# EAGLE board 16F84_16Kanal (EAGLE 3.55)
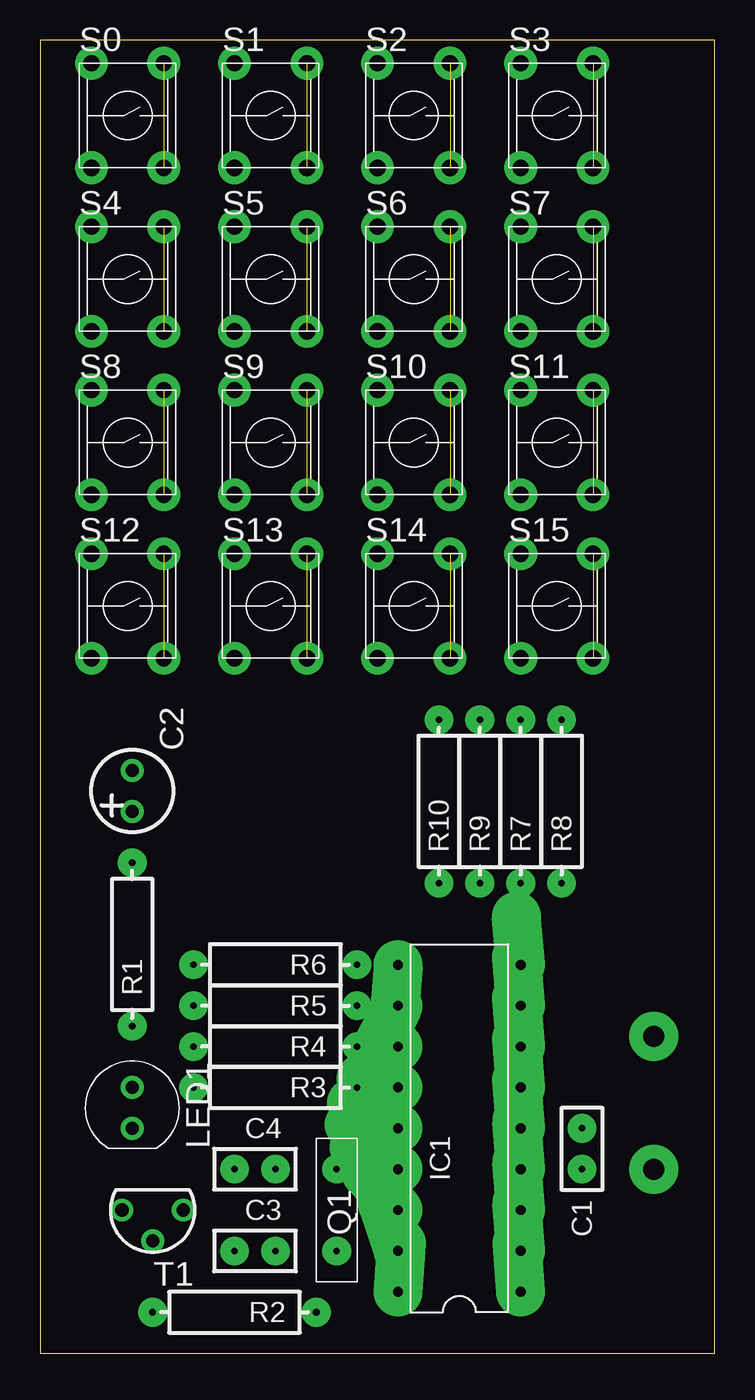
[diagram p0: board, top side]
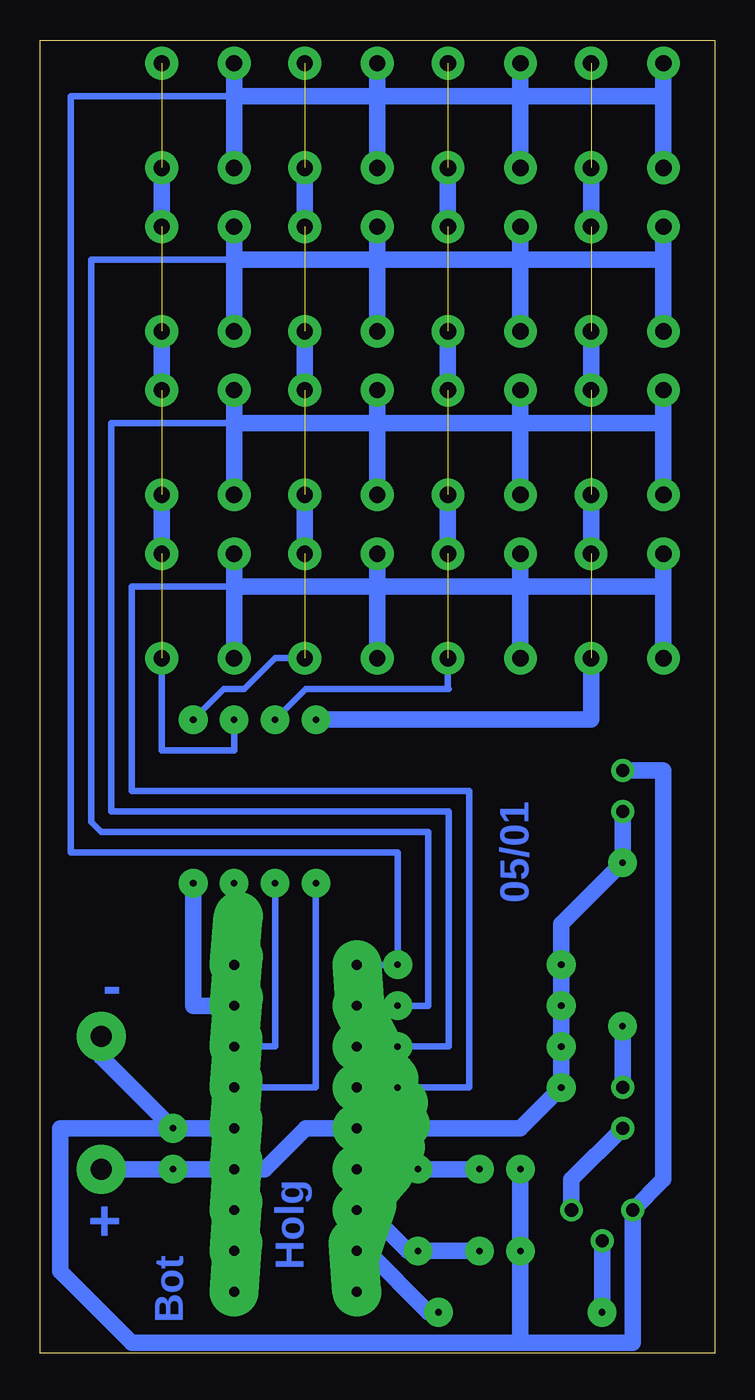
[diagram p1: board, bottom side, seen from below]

Size 41.89 x 81.58 mm. Coordinates in mm from the lower left corner, seen from the top.
Outline: 0,0 41.89,0 41.89,81.58 0,81.58 0,0
Copper layers used: Bottom

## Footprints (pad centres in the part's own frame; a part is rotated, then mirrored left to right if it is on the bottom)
RM2,5 = drill 0.406 pad 1.778 round:  0,0;  2.54,0
KO01 = drill 0.813 pad 1.422 round:  0,0;  2.54,0
L-18B = drill 0.61 pad 3.048 offset:  0,0;  2.54,0;  15.24,0;  17.78,0;  5.08,0;  7.62,0;  12.7,0;  10.16,0;  20.32,0;  20.32,7.62;  17.78,7.62;  15.24,7.62;  12.7,7.62;  10.16,7.62;  7.62,7.62;  5.08,7.62;  2.54,7.62;  0,7.62
D_5MM = drill 0.813 pad 1.422 round:  -1.27,0;  1.27,0
GEL = drill 1.295 pad 3.048 round:  0,0
ARZ_ST = drill 0.406 pad 1.778 round:  0,0;  5.08,0
S04 = drill 0.406 pad 1.778 round:  0,0;  10.16,0
USTAST = drill 1.016 pad 2.032 round:  0,0;  4.5,0;  4.5,6.5;  0,6.5
92 = drill 0.813 pad 1.422 round:  -0.635,0;  1.27,1.905;  3.175,0

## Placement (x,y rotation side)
C1  C100NK  [RM2,5]  33.66,13.97 270 top
C2  100u  [KO01]  5.71,33.66 90 top
C3  27p  [RM2,5]  12.06,6.35 0 top
C4  27p  [RM2,5]  12.06,11.43 0 top
IC1  16F84P  [L-18B]  29.84,3.81 90 top
LED1  LD274  [D_5MM]  5.71,15.24 270 top
N1  +  [GEL]  38.1,11.43 180 top
N2  -  [GEL]  38.1,19.68 180 top
Q1  4MHz  [ARZ_ST]  18.41,11.43 270 top
R1  ???  [S04]  5.71,20.32 90 top
R2  1k  [S04]  17.14,2.54 180 top
R3  100k  [S04]  19.68,16.51 180 top
R4  100k  [S04]  19.68,19.05 180 top
R5  100k  [S04]  19.68,21.59 180 top
R6  100k  [S04]  19.68,24.13 180 top
R7  1k  [S04]  29.84,29.21 90 top
R8  1k  [S04]  32.38,29.21 90 top
R9  1k  [S04]  27.3,29.21 90 top
R10  1k  [S04]  24.77,29.21 90 top
S0  [USTAST]  3.17,73.66 0 top
S1  [USTAST]  12.06,73.66 0 top
S2  [USTAST]  20.95,73.66 0 top
S3  [USTAST]  29.84,73.66 0 top
S4  [USTAST]  3.17,63.5 0 top
S5  [USTAST]  12.06,63.5 0 top
S6  [USTAST]  20.95,63.5 0 top
S7  [USTAST]  29.84,63.5 0 top
S8  [USTAST]  3.17,53.34 0 top
S9  [USTAST]  12.06,53.34 0 top
S10  [USTAST]  20.95,53.34 0 top
S11  [USTAST]  29.84,53.34 0 top
S12  [USTAST]  3.17,43.18 0 top
S13  [USTAST]  12.06,43.18 0 top
S14  [USTAST]  20.95,43.18 0 top
S15  [USTAST]  29.84,43.18 0 top
T1  BC337  [92]  8.26,8.89 180 top

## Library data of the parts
C1 C2 LED1 N1 N2 R1 R2 T1 = holgnorm
C3 C4 IC1 Q1 R3-R10 S0 S1-S15 = holg_plt

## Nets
+UB: C1. C2. IC1. N1. R1. R3. R4. R5. R6.
GND: C1. C2. C3. C4. IC1. N2. T1.
N$1: IC1. R6. S0. S1. S2. S3.
N$2: R2. T1.
N$3: IC1. R7.
N$4: LED1. T1.
N$5: LED1. R1.
N$6: IC1. R2.
N$7: C3. IC1. Q1.
N$8: C4. IC1. Q1.
N$9: IC1. R8.
N$10: IC1. R3. S12. S13. S14. S15.
N$11: IC1. R4. S8. S9. S10. S11.
N$12: IC1. R5. S4. S5. S6. S7.
N$13: IC1. R9.
N$14: R7. S3. S7. S11. S15.
N$15: IC1. R10.
N$17: R8. S2. S6. S10. S14.
N$18: R9. S1. S5. S9. S13.
N$19: R10. S0. S4. S8. S12.

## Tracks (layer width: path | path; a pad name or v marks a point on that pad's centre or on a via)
+UB
  Bottom 1.016: N1. C1. 29.84,11.43 27.94,11.43 25.4,13.97 22.23,13.97 12.06,13.97 R3. R4. R5. R6. 9.53,26.67 R1. 5.71,33.66
GND
  Bottom 0.406: 33.66,13.97 29.84,13.97
  Bottom 1.016: 12.06,11.43 12.06,6.35 12.06,0.64 | 12.06,0.64 5.08,0.64 T1. 3.17,10.79 3.17,36.2 C2. | 33.66,13.97 38.1,18.41 N2. | 33.66,13.97 29.84,13.97 | 33.66,13.97 40.64,13.97 40.64,5.08 36.2,0.64 12.06,0.64
N$1
  Bottom 0.406: 19.68,24.13 22.23,24.13 19.68,24.13 | 19.68,24.13 19.68,31.11 40.01,31.11 40.01,78.11 29.84,78.11
  Bottom 1.016: 3.17,78.11 S0. | 12.06,78.11 3.17,78.11 | 20.95,78.11 12.06,78.11 | 29.84,78.11 20.95,78.11 | 12.06,78.11 S1. | 20.95,78.11 S2. | 29.84,78.11 S3. | 3.17,78.11 3.17,73.66 | 12.06,78.11 12.06,73.66 | 20.95,78.11 20.95,73.66 | 29.84,78.11 29.84,73.66
N$2
  Bottom 1.016: R2. 6.99,6.99
N$3
  Bottom 1.016: 29.84,24.13 29.84,29.21
N$4
  Bottom 1.016: 8.89,8.89 8.89,10.79 LED1.
N$5
  Bottom 1.016: 5.71,16.51 5.71,20.32
N$6
  Bottom 0.406: 17.14,2.54 17.78,2.54
  Bottom 1.016: 22.23,6.35 21.59,6.35 17.78,2.54
N$7
  Bottom 0.406: Q1. 19.05,6.35
  Bottom 1.016: C3. Q1. | 19.05,6.35 21.59,8.89 22.23,8.89
N$8
  Bottom 1.016: 22.23,11.43 18.41,11.43 C4.
N$9
  Bottom 1.016: 29.84,21.59 32.38,21.59 32.38,29.21
N$10
  Bottom 0.406: 19.68,16.51 22.23,16.51 19.68,16.51 | 19.68,16.51 15.24,16.51 15.24,34.92 36.2,34.92 36.2,47.62 29.84,47.62
  Bottom 1.016: 3.17,47.62 S12. | 12.06,47.62 3.17,47.62 | 20.95,47.62 12.06,47.62 | 29.84,47.62 20.95,47.62 | 12.06,47.62 S13. | 20.95,47.62 S14. | 29.84,47.62 S15. | 3.17,47.62 3.17,43.18 | 12.06,47.62 12.06,43.18 | 20.95,47.62 20.95,43.18 | 29.84,47.62 29.84,43.18
N$11
  Bottom 0.406: 19.68,19.05 22.23,19.05 | 19.68,19.05 22.23,19.05 | 19.68,19.05 22.23,19.05 | 19.68,19.05 16.51,19.05 16.51,33.66 37.47,33.66 37.47,57.78 29.84,57.78
  Bottom 1.016: 3.17,57.78 S8. | 12.06,57.78 3.17,57.78 | 20.95,57.78 12.06,57.78 | 29.84,57.78 20.95,57.78 | 12.06,57.78 S9. | 20.95,57.78 S10. | 29.84,57.78 S11. | 3.17,57.78 3.17,53.34 | 12.06,57.78 12.06,53.34 | 20.95,57.78 20.95,53.34 | 29.84,57.78 29.84,53.34
N$12
  Bottom 0.406: 19.68,21.59 22.23,21.59 19.68,21.59 | 19.68,21.59 17.78,21.59 17.78,32.38 38.1,32.38 38.73,33.02 38.73,67.94 29.84,67.94
  Bottom 1.016: 3.17,67.94 S4. | 12.06,67.94 3.17,67.94 | 20.95,67.94 12.06,67.94 | 29.84,67.94 20.95,67.94 | 12.06,67.94 S5. | 20.95,67.94 S6. | 29.84,67.94 S7. | 3.17,67.94 3.17,63.5 | 12.06,67.94 12.06,63.5 | 20.95,67.94 20.95,63.5 | 29.84,67.94 29.84,63.5
N$13
  Bottom 0.406: 29.84,19.05 27.3,19.05 27.3,29.21
N$14  (4 unrouted)
  Bottom 0.406: 34.34,43.18 34.34,37.47 29.84,37.47 R7. | 34.34,51.38 34.29,51.44 34.34,51.49 | 34.34,61.65 34.29,61.59 34.34,61.54 | 34.34,71.7 34.29,71.75 34.34,71.81
  Bottom 1.016: 34.34,49.68 34.34,51.38 | 34.34,51.49 34.34,53.34 | 34.34,61.65 34.34,63.5 | 34.34,59.84 34.34,61.54 | 34.34,70 34.34,71.7 | 34.34,73.66 34.34,71.81
N$15
  Bottom 0.406: 29.84,16.51 24.77,16.51 24.77,29.21
N$17  (4 unrouted)
  Bottom 0.406: 25.45,43.18 27.3,43.18 29.21,41.27 30.48,41.27 R8. | 25.45,51.38 25.4,51.44 25.45,51.49 | 25.45,61.65 25.4,61.59 25.45,61.54 | 25.45,71.7 25.4,71.75 25.45,71.81
  Bottom 1.016: 25.45,49.68 25.45,51.38 | 25.45,51.49 25.45,53.34 | 25.45,61.65 25.45,63.5 | 25.45,59.84 25.45,61.54 | 25.45,70 25.45,71.7 | 25.45,73.66 25.45,71.81
N$18  (4 unrouted)
  Bottom 0.406: R9. 25.4,41.27 16.57,41.27 | 16.57,41.27 16.57,43.18 | 16.57,41.27 16.51,41.27 | 16.57,51.38 16.51,51.44 16.57,51.49 | 16.57,61.65 16.51,61.59 16.57,61.54 | 16.57,71.7 16.51,71.75 16.57,71.81
  Bottom 1.016: 16.57,49.68 16.57,51.38 | 16.57,51.49 16.57,53.34 | 16.57,61.65 16.57,63.5 | 16.57,59.84 16.57,61.54 | 16.57,70 16.57,71.7 | 16.57,73.66 16.57,71.81
N$19  (4 unrouted)
  Bottom 0.406: 7.67,39.37 7.62,40.64 | 7.67,51.38 7.62,51.44 7.67,51.49 | 7.67,61.65 7.62,61.59 7.67,61.54 | 7.67,71.7 7.62,71.75 7.67,71.81
  Bottom 1.016: R10. 7.67,39.37 7.67,43.18 | 7.67,49.68 7.67,51.38 | 7.67,51.49 7.67,53.34 | 7.67,61.65 7.67,63.5 | 7.67,59.84 7.67,61.54 | 7.67,70 7.67,71.7 | 7.67,73.66 7.67,71.81

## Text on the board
Bottom: 05/01 | - | Holg | + | Bot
